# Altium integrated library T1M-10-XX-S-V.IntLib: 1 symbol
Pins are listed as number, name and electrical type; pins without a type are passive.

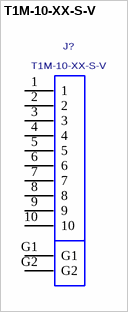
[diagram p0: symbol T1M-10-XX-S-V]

## T1M-10-XX-S-V
designator J?
1MM TERMINAL STRIP, 10PINS.; MANUFACTURER: SAMTEC
footprint T1M-10-XX-S-V
pins: 1, 2, 3, 4, 5, 6, 7, 8, 9, 10, G1, G2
